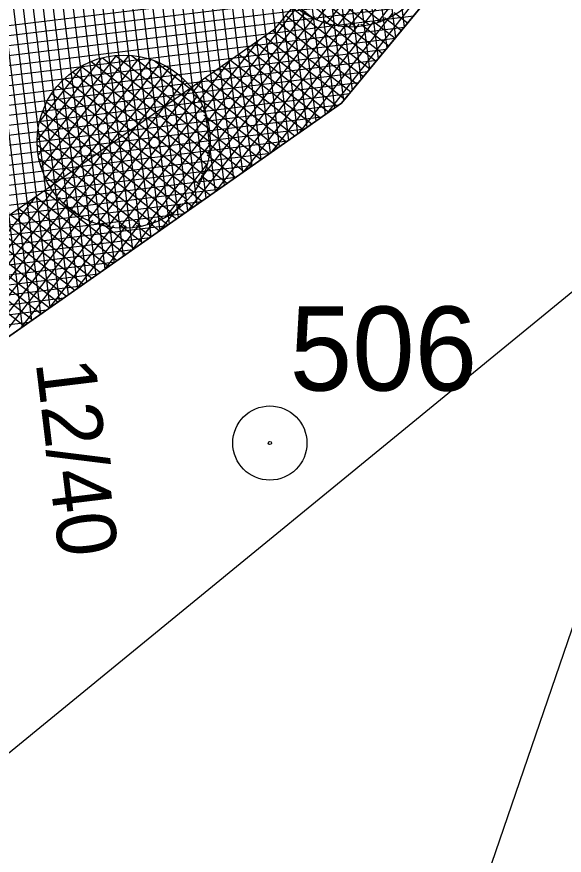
# Model space of a CAD drawing. Extents: x -566982 to -566809, y -1095912 to -1095685.
# Drawn here: x -566860.47 to -566849.4, y -1095812.81 to -1095795.86 of the extents above; entities that cross this region are included whole.
import ezdxf

# ---------------------------------------------------------------- set-up
doc = ezdxf.new("R2010")
doc.units = 0
for name, color, linetype in [('Vrstva 1', 7, 'Continuous'), ('Vrstva 17', 7, 'Continuous'), ('Vrstva 24', 7, 'Continuous'), ('Vrstva 40', 7, 'Continuous'), ('Vrstva 41', 7, 'Continuous'), ('Vrstva 42', 7, 'Continuous'), ('Vrstva 43', 7, 'Continuous'), ('Vrstva 44', 7, 'Continuous')]:
    doc.layers.add(name, color=color, linetype=linetype)

msp = doc.modelspace()

# ---------------------------------------------------------------- linework, layer by layer
at = {"layer": 'Vrstva 1'}
for p, q in [((-566839.47, -1095780.13), (-566853.9, -1095797.61)), ((-566853.9, -1095797.61), (-566880.71, -1095816.4)), ((-566865.42, -1095814.66), (-566845.99, -1095798.76)), ((-566851.169, -1095813.866), (-566845.99, -1095798.76))]:
    msp.add_line(p, q, dxfattribs=at)
at = {"layer": 'Vrstva 24'}
for radius in [0.75, 0.0327]:
    msp.add_circle((-566855.35, -1095804.48), radius, dxfattribs=at)
at = {"layer": 'Vrstva 41'}
for p, q in [((-566845.057, -1095786.133), (-566854.205, -1095797.824)), ((-566854.784, -1095795.643), (-566856.637, -1095798.012)), ((-566854.622, -1095795.76), (-566856.6, -1095798.288)), ((-566854.902, -1095795.683), (-566853.327, -1095796.916)), ((-566852.876, -1095795.801), (-566854.767, -1095798.218)), ((-566852.834, -1095795.778), (-566852.563, -1095795.99)), ((-566854.041, -1095795.992), (-566857.017, -1095799.794)), ((-566854.251, -1095795.936), (-566856.794, -1095799.186)), ((-566854.444, -1095795.858), (-566856.615, -1095798.633)), ((-566853.253, -1095795.958), (-566855.329, -1095798.612)), ((-566855.157, -1095795.992), (-566853.582, -1095797.224)), ((-566855.03, -1095795.837), (-566853.454, -1095797.07)), ((-566854.259, -1095795.933), (-566853.2, -1095796.762)), ((-566853.253, -1095795.958), (-566852.817, -1095796.299)), ((-566853.03, -1095795.879), (-566852.69, -1095796.144)), ((-566853.806, -1095796.016), (-566856.454, -1095799.4)), ((-566853.549, -1095796.012), (-566855.892, -1095799.006)), ((-566855.29, -1095796.141), (-566853.709, -1095797.379)), ((-566853.827, -1095796.016), (-566853.072, -1095796.607)), ((-566853.51, -1095796.011), (-566852.945, -1095796.453)), ((-566855.461, -1095796.261), (-566853.836, -1095797.533)), ((-566855.596, -1095796.356), (-566856.709, -1095797.779)), ((-566855.804, -1095796.501), (-566854.157, -1095797.79)), ((-566855.633, -1095796.381), (-566853.986, -1095797.67)), ((-566855.975, -1095796.621), (-566854.328, -1095797.91)), ((-566856.158, -1095796.75), (-566856.803, -1095797.574)), ((-566856.146, -1095796.741), (-566854.499, -1095798.03)), ((-566856.488, -1095796.981), (-566854.842, -1095798.27)), ((-566856.317, -1095796.861), (-566854.671, -1095798.15)), ((-566856.72, -1095797.144), (-566856.915, -1095797.393)), ((-566856.66, -1095797.101), (-566855.013, -1095798.39)), ((-566856.831, -1095797.221), (-566855.184, -1095798.51)), ((-566856.893, -1095797.427), (-566855.355, -1095798.63)), ((-566856.684, -1095797.844), (-566855.527, -1095798.75)), ((-566856.613, -1095798.154), (-566855.698, -1095798.87)), ((-566856.597, -1095798.42), (-566855.869, -1095798.99)), ((-566856.619, -1095798.657), (-566856.04, -1095799.11)), ((-566856.666, -1095798.874), (-566856.211, -1095799.23)), ((-566856.739, -1095799.071), (-566856.383, -1095799.35)), ((-566859.717, -1095799.351), (-566861.139, -1095801.168)), ((-566859.912, -1095799.381), (-566858.266, -1095800.67)), ((-566856.832, -1095799.252), (-566856.554, -1095799.47)), ((-566860.095, -1095799.509), (-566861.21, -1095800.935)), ((-566859.591, -1095799.514), (-566861.101, -1095801.444)), ((-566860.084, -1095799.501), (-566858.437, -1095800.79)), ((-566856.944, -1095799.418), (-566856.725, -1095799.59)), ((-566859.449, -1095799.658), (-566861.116, -1095801.787)), ((-566860.255, -1095799.621), (-566858.608, -1095800.91)), ((-566857.166, -1095799.661), (-566857.579, -1095800.188)), ((-566857.223, -1095799.708), (-566857.067, -1095799.83)), ((-566857.074, -1095799.571), (-566856.896, -1095799.71)), ((-566859.123, -1095799.89), (-566861.515, -1095802.947)), ((-566859.294, -1095799.784), (-566861.289, -1095802.333)), ((-566860.597, -1095799.861), (-566858.951, -1095801.15)), ((-566860.426, -1095799.741), (-566858.779, -1095801.03)), ((-566857.391, -1095799.831), (-566857.239, -1095799.95)), ((-566858.936, -1095799.976), (-566860.953, -1095802.553)), ((-566860.768, -1095799.981), (-566859.122, -1095801.27)), ((-566858.734, -1095800.041), (-566860.391, -1095802.159)), ((-566858.75, -1095800.037), (-566858.095, -1095800.55)), ((-566857.991, -1095800.066), (-566858.704, -1095800.977)), ((-566857.661, -1095799.969), (-566858.141, -1095800.582)), ((-566857.799, -1095800.019), (-566857.581, -1095800.19)), ((-566857.581, -1095799.936), (-566857.41, -1095800.07)), ((-566861.111, -1095800.221), (-566859.464, -1095801.51)), ((-566860.94, -1095800.101), (-566859.293, -1095801.39)), ((-566858.512, -1095800.083), (-566859.828, -1095801.765)), ((-566858.262, -1095800.088), (-566859.266, -1095801.371)), ((-566858.358, -1095800.089), (-566857.923, -1095800.43)), ((-566858.05, -1095800.076), (-566857.752, -1095800.31)), ((-566861.282, -1095800.341), (-566859.635, -1095801.63)), ((-566861.453, -1095800.461), (-566859.807, -1095801.75)), ((-566861.228, -1095800.891), (-566859.978, -1095801.87)), ((-566861.129, -1095801.223), (-566860.149, -1095801.99)), ((-566861.097, -1095801.502), (-566860.32, -1095802.11))]:
    msp.add_line(p, q, dxfattribs=at)
at = {"layer": 'Vrstva 42'}
msp.add_lwpolyline([(-566834.15, -1095760.69), (-566836.072, -1095760.136), (-566841.286, -1095779.189), (-566855.268, -1095796.126), (-566881.984, -1095814.851), (-566891.818, -1095824.318), (-566954.342, -1095716.292), (-566956.66, -1095716.28), (-566892.27, -1095827.53), (-566880.71, -1095816.4), (-566853.9, -1095797.61), (-566839.47, -1095780.13)], close=True, dxfattribs=at)
at = {"layer": 'Vrstva 43'}
for p, q in [((-566854.304, -1095782.391), (-566852.634, -1095796.076)), ((-566854.48, -1095782.604), (-566852.81, -1095796.289)), ((-566854.655, -1095782.816), (-566852.985, -1095796.502)), ((-566854.831, -1095783.029), (-566853.161, -1095796.714)), ((-566855.006, -1095783.242), (-566853.336, -1095796.927)), ((-566855.182, -1095783.454), (-566853.512, -1095797.14)), ((-566855.357, -1095783.667), (-566853.687, -1095797.352)), ((-566855.533, -1095783.879), (-566853.863, -1095797.565)), ((-566855.708, -1095784.092), (-566854.046, -1095797.712)), ((-566855.884, -1095784.305), (-566854.232, -1095797.843)), ((-566856.059, -1095784.517), (-566854.417, -1095797.973)), ((-566856.235, -1095784.73), (-566854.603, -1095798.103)), ((-566856.41, -1095784.943), (-566854.789, -1095798.233)), ((-566856.586, -1095785.155), (-566854.974, -1095798.363)), ((-566856.762, -1095785.368), (-566855.16, -1095798.493)), ((-566856.937, -1095785.581), (-566855.345, -1095798.623)), ((-566857.113, -1095785.793), (-566855.531, -1095798.753)), ((-566857.288, -1095786.006), (-566855.717, -1095798.883)), ((-566857.464, -1095786.219), (-566855.902, -1095799.013)), ((-566857.639, -1095786.431), (-566856.088, -1095799.143)), ((-566857.815, -1095786.644), (-566856.274, -1095799.274)), ((-566857.99, -1095786.857), (-566856.459, -1095799.404)), ((-566858.166, -1095787.069), (-566856.645, -1095799.534)), ((-566858.341, -1095787.282), (-566856.83, -1095799.664)), ((-566858.517, -1095787.495), (-566857.016, -1095799.794)), ((-566858.692, -1095787.707), (-566857.202, -1095799.924)), ((-566858.868, -1095787.92), (-566857.387, -1095800.054)), ((-566859.043, -1095788.133), (-566857.573, -1095800.184)), ((-566859.219, -1095788.345), (-566857.758, -1095800.314)), ((-566859.395, -1095788.558), (-566857.944, -1095800.444)), ((-566859.57, -1095788.771), (-566858.13, -1095800.574)), ((-566859.746, -1095788.983), (-566858.315, -1095800.704)), ((-566859.921, -1095789.196), (-566858.501, -1095800.835)), ((-566860.097, -1095789.408), (-566858.686, -1095800.965)), ((-566860.272, -1095789.621), (-566858.872, -1095801.095)), ((-566860.448, -1095789.834), (-566859.058, -1095801.225)), ((-566860.623, -1095790.046), (-566859.243, -1095801.355)), ((-566860.802, -1095790.236), (-566859.429, -1095801.485)), ((-566860.987, -1095790.366), (-566859.614, -1095801.615)), ((-566861.173, -1095790.496), (-566859.8, -1095801.745)), ((-566861.358, -1095790.626), (-566859.986, -1095801.875)), ((-566861.73, -1095790.887), (-566860.357, -1095802.135)), ((-566861.544, -1095790.756), (-566860.171, -1095802.005)), ((-566870.867, -1095797.29), (-566851.706, -1095794.952)), ((-566871.215, -1095797.534), (-566851.891, -1095795.176)), ((-566871.563, -1095797.778), (-566852.076, -1095795.4)), ((-566871.911, -1095798.022), (-566852.261, -1095795.624)), ((-566872.259, -1095798.266), (-566852.446, -1095795.848)), ((-566872.607, -1095798.51), (-566852.631, -1095796.072)), ((-566872.955, -1095798.754), (-566852.815, -1095796.296)), ((-566873.303, -1095798.998), (-566853, -1095796.52)), ((-566873.652, -1095799.242), (-566853.185, -1095796.744)), ((-566874, -1095799.486), (-566853.37, -1095796.968)), ((-566874.348, -1095799.73), (-566853.555, -1095797.192)), ((-566874.696, -1095799.974), (-566853.74, -1095797.417)), ((-566875.044, -1095800.218), (-566853.947, -1095797.643)), ((-566875.392, -1095800.462), (-566854.296, -1095797.887)), ((-566875.74, -1095800.706), (-566854.644, -1095798.131)), ((-566876.088, -1095800.95), (-566854.992, -1095798.375)), ((-566876.436, -1095801.194), (-566855.34, -1095798.619)), ((-566876.784, -1095801.438), (-566855.688, -1095798.863)), ((-566877.133, -1095801.681), (-566856.036, -1095799.107)), ((-566877.481, -1095801.925), (-566856.384, -1095799.351)), ((-566877.829, -1095802.169), (-566856.732, -1095799.595)), ((-566878.177, -1095802.413), (-566857.08, -1095799.839)), ((-566878.525, -1095802.657), (-566857.428, -1095800.083)), ((-566878.873, -1095802.901), (-566857.776, -1095800.327)), ((-566879.221, -1095803.145), (-566858.125, -1095800.571)), ((-566879.569, -1095803.389), (-566858.473, -1095800.815)), ((-566879.917, -1095803.633), (-566858.821, -1095801.059)), ((-566880.265, -1095803.877), (-566859.169, -1095801.303)), ((-566880.614, -1095804.121), (-566859.517, -1095801.547)), ((-566880.962, -1095804.365), (-566859.865, -1095801.791)), ((-566881.31, -1095804.609), (-566860.213, -1095802.035))]:
    msp.add_line(p, q, dxfattribs=at)
msp.add_lwpolyline([(-566834.15, -1095760.69), (-566843.76, -1095757.92), (-566848.55, -1095775.42), (-566860.75, -1095790.2), (-566887.09, -1095808.66), (-566890.01, -1095811.47), (-566945.07, -1095716.34), (-566956.66, -1095716.28), (-566892.27, -1095827.53), (-566880.71, -1095816.4), (-566853.9, -1095797.61), (-566839.47, -1095780.13)], close=True, dxfattribs=at)
at = {"layer": 'Vrstva 44'}
for p, q in [((-566852.321, -1095793.265), (-566854.404, -1095795.927)), ((-566852.204, -1095793.44), (-566854.207, -1095796)), ((-566852.104, -1095793.637), (-566853.99, -1095796.047)), ((-566852.027, -1095793.864), (-566853.754, -1095796.07)), ((-566855.451, -1095794.115), (-566853.097, -1095795.957)), ((-566851.977, -1095794.123), (-566853.487, -1095796.054)), ((-566855.463, -1095794.36), (-566853.333, -1095796.026)), ((-566851.969, -1095794.438), (-566853.179, -1095795.985)), ((-566855.434, -1095794.636), (-566853.606, -1095796.067)), ((-566855.34, -1095794.964), (-566853.946, -1095796.055)), ((-566855.062, -1095795.435), (-566854.474, -1095795.895)), ((-566858.458, -1095796.644), (-566860.034, -1095798.657)), ((-566858.203, -1095796.642), (-566859.975, -1095798.907)), ((-566857.971, -1095796.67), (-566859.892, -1095799.125)), ((-566858.472, -1095796.646), (-566856.577, -1095798.129)), ((-566858.148, -1095796.645), (-566856.653, -1095797.815)), ((-566858.753, -1095796.696), (-566860.054, -1095798.358)), ((-566859.119, -1095796.838), (-566860.005, -1095797.972)), ((-566857.76, -1095796.725), (-566859.787, -1095799.315)), ((-566857.567, -1095796.803), (-566859.666, -1095799.485)), ((-566858.966, -1095796.767), (-566856.575, -1095798.638)), ((-566858.737, -1095796.692), (-566856.558, -1095798.398)), ((-566857.688, -1095796.751), (-566856.862, -1095797.397)), ((-566857.388, -1095796.899), (-566859.53, -1095799.636)), ((-566857.224, -1095797.013), (-566859.379, -1095799.768)), ((-566859.344, -1095796.979), (-566856.691, -1095799.055)), ((-566859.166, -1095796.865), (-566856.621, -1095798.856)), ((-566859.502, -1095797.11), (-566856.78, -1095799.24)), ((-566857.073, -1095797.145), (-566859.214, -1095799.881)), ((-566859.64, -1095797.256), (-566856.887, -1095799.409)), ((-566856.938, -1095797.297), (-566859.034, -1095799.976)), ((-566859.76, -1095797.416), (-566857.013, -1095799.565)), ((-566856.818, -1095797.469), (-566858.84, -1095800.052)), ((-566859.862, -1095797.59), (-566857.158, -1095799.706)), ((-566856.715, -1095797.661), (-566858.627, -1095800.105)), ((-566859.946, -1095797.778), (-566857.322, -1095799.831)), ((-566860.008, -1095797.984), (-566857.506, -1095799.941)), ((-566856.632, -1095797.88), (-566858.395, -1095800.133)), ((-566856.576, -1095798.133), (-566858.136, -1095800.127)), ((-566860.045, -1095798.209), (-566857.714, -1095800.033)), ((-566860.054, -1095798.455), (-566857.954, -1095800.099)), ((-566856.559, -1095798.435), (-566857.84, -1095800.073)), ((-566860.019, -1095798.737), (-566858.234, -1095800.134)), ((-566856.613, -1095798.829), (-566857.467, -1095799.92)), ((-566859.915, -1095799.072), (-566858.586, -1095800.112)), ((-566859.563, -1095799.601), (-566859.183, -1095799.899))]:
    msp.add_line(p, q, dxfattribs=at)
for centre in [(-566853.715, -1095794.321), (-566858.306, -1095798.387)]:
    msp.add_circle(centre, 1.75, dxfattribs=at)

# ---------------------------------------------------------------- texts
at = {"layer": 'Vrstva 17'}
msp.add_text('506', height=1.7, dxfattribs=at).set_placement((-566854.95, -1095803.42))
at = {"layer": 'Vrstva 40'}
msp.add_text('12/40', height=1.2, rotation=276.9575, dxfattribs=at).set_placement((-566860.089, -1095802.846))

doc.saveas('drawing.dxf')
